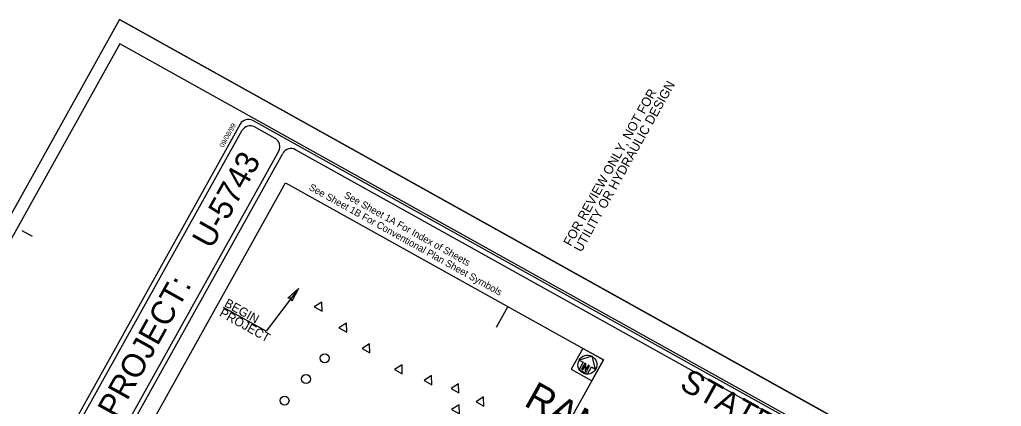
# Model space of a CAD drawing. Extents: x 1754939 to 1770240, y 706534 to 717510.
# Drawn here: x 1760772 to 1767067, y 715030 to 717510 of the extents above; entities that cross this region are included whole.
import ezdxf

# ---------------------------------------------------------------- set-up
doc = ezdxf.new("R2010")
doc.units = 0
for name, color, linetype in [('Culvert Barrel', 7, 'Continuous'), ('Culvert Wing', 7, 'Continuous'), ('Prop Conc Drive Radius Type', 7, 'Continuous'), ('Prop DSN Text', 7, 'Continuous'), ('Prop Guardrail Anchor Unit CELL', 7, 'Continuous'), ('Prop Lane Arrow CELL', 7, 'Continuous'), ('Scratch_Level_0', 7, 'Continuous'), ('Scratch_Level_3', 7, 'Continuous'), ('Sheet PE Seal Cell', 7, 'Continuous')]:
    doc.layers.add(name, color=color, linetype=linetype)

msp = doc.modelspace()

# ---------------------------------------------------------------- linework, layer by layer
at = {"layer": 'Culvert Barrel'}
for q in [(1758201.2, 711744), (1770239.7, 712594.3)]:
    msp.add_line((1761412.2, 717510.1), q, dxfattribs=at)
at = {"layer": 'Culvert Wing'}
msp.add_lwpolyline([(1770239.7, 712594.3), (1761412.2, 717510.1), (1758201.2, 711744), (1767028.7, 706828.1)], close=True, dxfattribs=at)
at = {"layer": 'Prop Conc Drive Radius Type'}
for p, q in [((1759455.4, 711320.2), (1762433, 716667)), ((1760021.7, 712275.4), (1762459.2, 716652.4)), ((1760786.7, 716158.7), (1760852.2, 716122.2))]:
    msp.add_line(p, q, dxfattribs=at)
for points in [[(1770025.3, 712542), (1762267, 716862.5)], [(1762185.5, 716839.2), (1759178.7, 711439.9)], [(1762197.2, 716798.4), (1759219.6, 711451.6)], [(1762409.7, 716748.6), (1762278.7, 716821.6)], [(1769984.4, 712530.4), (1762540.8, 716675.6)]]:
    msp.add_lwpolyline(points, dxfattribs=at)
for centre, start, end in [((1762238, 716810.2), 60.88754, 150.88754), ((1762249.7, 716769.4), 60.88754, 150.88754), ((1762380.7, 716696.4), 330.88754, 60.88754), ((1762511.8, 716623.5), 60.88754, 150.88754)]:
    msp.add_arc(centre, 60, start, end, dxfattribs=at)
at = {"layer": 'Prop Guardrail Anchor Unit CELL'}
msp.add_lwpolyline([(1762491.8, 715723.3), (1762559.1, 715786.6), (1762517, 715703.7), (1762511, 715722.7)], close=True, dxfattribs=at)
at = {"layer": 'Prop Lane Arrow CELL'}
msp.add_lwpolyline([(1758334.8, 711823.6), (1767070.6, 706958.9), (1770150.6, 712489.7), (1761414.8, 717354.5), (1758334.8, 711823.6)], dxfattribs=at)
at = {"layer": 'Scratch_Level_0'}
for p, q in [((1762559.1, 715786.6), (1762352.6, 715512.4)), ((1762352.6, 715512.4), (1762079.6, 715663.4))]:
    msp.add_line(p, q, dxfattribs=at)
at = {"layer": 'Scratch_Level_3'}
for p, q in [((1764442.2, 715351.1), (1764359.8, 715327)), ((1764465.1, 715268.4), (1764442.2, 715351.1)), ((1764359.8, 715327), (1764386.1, 715312.3)), ((1764386.1, 715312.3), (1764360.4, 715266.1)), ((1764413, 715236.8), (1764438.8, 715283)), ((1764438.8, 715283), (1764465.1, 715268.4)), ((1764360.4, 715266.1), (1764413, 715236.8))]:
    msp.add_line(p, q, dxfattribs=at)
for points in [[(1764309.5, 715267.5), (1764441, 715194.3), (1764515.4, 715327.8), (1764383.8, 715401.1)], [(1764396.3, 715306.3), (1764375.4, 715268.8), (1764382.7, 715264.7), (1764397.4, 715291), (1764398.4, 715256), (1764405.9, 715251.8), (1764426.8, 715289.3), (1764419.3, 715293.5), (1764404.7, 715267.2), (1764403.6, 715302.2)]]:
    msp.add_lwpolyline(points, close=True, dxfattribs=at)
msp.add_ellipse((1764412.4, 715297.7), major_axis=(29.7, 53.4), ratio=0.985213, dxfattribs=at)
at = {"layer": 'Sheet PE Seal Cell'}
msp.add_line((1763902.3, 715669.2), (1763827.9, 715535.7), dxfattribs=at)
for points in [[(1762475.9, 716463.6), (1764515.4, 715327.8), (1763647.8, 713769.9), (1761608.3, 714905.6)], [(1762709.6, 715697.8), (1762661.3, 715667.1), (1762711.3, 715639.3)], [(1762867.4, 715564.4), (1762819.1, 715533.7), (1762869, 715505.9)], [(1763016, 715431.2), (1762967.7, 715400.6), (1763017.7, 715372.7)], [(1763224, 715296.9), (1763175.7, 715266.3), (1763225.6, 715238.4)], [(1763413.4, 715227), (1763365.1, 715196.3), (1763415.1, 715168.5)], [(1763586.9, 715174.4), (1763538.6, 715143.7), (1763588.5, 715115.9)], [(1763747.4, 715090.6), (1763699.1, 715059.9), (1763749.1, 715032.1)], [(1763590.3, 715039.8), (1763542, 715009.1), (1763592, 714981.3)]]:
    msp.add_lwpolyline(points, close=True, dxfattribs=at)
for centre in [(1762728.2, 715338.7), (1762608.2, 715204.5), (1762470.4, 715067.2)]:
    msp.add_circle(centre, 28.8, dxfattribs=at)

# ---------------------------------------------------------------- texts
at = {"layer": 'Prop Conc Drive Radius Type'}
for s, height, rotation, p in [('09/08/99', 31.5, 60.88754, (1762078.3, 716686.8)), ('U-5743  ', 150, 60.88754, (1762001.4, 716032.4)), ('See Sheet 1B For Conventional Plan Sheet Symbols', 45, 330.88754, (1762622.7, 716421.4)), ('See Sheet 1A For Index of Sheets', 45, 330.88754, (1762848, 716371.6)), ('TIP PROJECT:', 150, 60.88754, (1761216.8, 714623.6)), ('STATE OF NORTH CAROLINA', 149.999, 330.88754, (1764996.4, 715146))]:
    msp.add_text(s, height=height, rotation=rotation, dxfattribs=at).set_placement(p)
at = {"layer": 'Prop DSN Text'}
for s, p in [('BEGIN', (1762079.9, 715674.2)), ('PROJECT', (1762048, 715612.3))]:
    msp.add_text(s, height=56.9, rotation=330.88765, dxfattribs=at).set_placement(p)
at = {"layer": 'Scratch_Level_3'}
for s, height, rotation, p in [('UTILITY OR HYDRAULIC DESIGN', 59.062, 60.88772, (1764374, 716014.7)), ('FOR REVIEW ONLY, NOT FOR', 59.062, 60.88772, (1764306.3, 716052.4)), ('       RANDOLPH COUNTY       ', 180, 330.88754, (1763589.6, 715265.8))]:
    msp.add_text(s, height=height, rotation=rotation, dxfattribs=at).set_placement(p)

doc.saveas('drawing.dxf')
